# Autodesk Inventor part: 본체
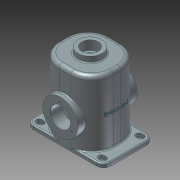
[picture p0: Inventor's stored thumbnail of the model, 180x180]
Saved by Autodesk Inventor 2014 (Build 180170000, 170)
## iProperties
Company: 한국ATC센터
Created: 2014-10
Part Number: 본체
Document SubType Name: Modeling
Designer: 한국ATC센터
Density: 2.71 g/cm^3
Material: 알루미늄 6061
Mass: 2952.11 g
Surface Area: 2149.43 cm^2
Volume: 1089.34 cm^3
Appearance: 청회색(연함)
Author: KYOUNG IL JANG
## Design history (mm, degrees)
sketch "스케치1"
  geometry: L1 (-70, 65)-(70, 65); L2 (70, 65)-(70, -65); L3 (70, -65)-(-70, -65); L4 (-70, -65)-(-70, 65); 3 further points
  constraints: 8 end point, 2 midpoint, 2 parallel, 1 horizontal, 1 horizontal alignment, 1 perpendicular, 1 vertical alignment
  dimensions: "d0" = 140 distance of L2.end L3.end; "d68" = 130 distance of L3.end L1.start
extrude "돌출1" new body sketch "스케치1" distance "d1" = 180; taper "d2" = 0 deg
fillet "모깎기1" dims "d3" = 55
feature "쉘1" dims "d4" = 10
sketch "스케치2"
  geometry: L1 (-70, 10)-(-70, -10) reference; L2 (-15, -65)-(-82, -65); L3 (-82, 65)-(-15, 65); L4 (-83, 57)-(-78, 57); L5 (-78, 41)-(-83, 41); L6 (-100, 47)-(-100, -47); A1 r 55 centre (-15, 10) between (-15, 65) and (-70, 10) reference; A2 r 55 centre (-15, -10) between (-70, -10) and (-15, -65) reference; A3 r 8 centre (-78, 49) between (-78, 41) and (-78, 57); A4 r 8 centre (-83, 49) between (-83, 57) and (-83, 41); A5 r 18 centre (-82, 47) between (-82, 65) and (-100, 47); A6 r 18 centre (-82, -47) between (-100, -47) and (-82, -65); 1 further point
  constraints: 10 end point, 9 tangent, 8 point on circle, 4 centre point, 2 parallel, 2 perpendicular, 1 equal radius
  dimensions: "d6" = 49 vertical distance of point (0, 0) A3.centre; "d8" = 16 distance between parallel lines of L4 L5; "d64" = 18 radius of A5; "d65" = 8 distance from line of A3.centre L1; "d66" = 30 distance between parallel lines of L6 L1; "d67" = 5 distance of A4.centre A3.centre
extrude "돌출2" join sketch "스케치2" distance "d9" = 10; taper "d10" = 0 deg
extrude "돌출3" cut sketch "스케치2" stored distance "d11" = 10; taper "d12" = 0 deg
sketch "스케치3"
  geometry: L1 (-65, 10)-(-65, 180) reference; L2 (-55, 0)-(-55, 170) reference; L3 (-77, 75)-(-45, 75); L4 (10, 0)-(-10, 0) reference; L5 (-77, 75)-(-77, 120.5); L6 (-77, 120.5)-(-55, 120.5); L7 (-55, 120.5)-(-45, 110.5); L8 (-45, 110.5)-(-45, 75); 3 further points
  constraints: 10 end point, 4 perpendicular, 1 point on line
  dimensions: "d13" = 75 distance between parallel lines of L3 L4; "d14" = 12 distance from line of L1 L3.start; "d15" = 10 distance from line of L3.end L2; "d16" = 91 diameter of L6 L3; "d17" = 135 deg angle of L7 L2
revolve "회전1" sketch "스케치3" stored, may be unused: angle "d18" = 90 deg
sketch "스케치4"
  geometry: C1 r 45.5 at (0, 0) reference; 2 further points
  constraints: 1 vertical alignment
  dimensions: "d19" = 35 distance of C1.centre point (0, 35)
hole "구멍1" sketch "스케치4" at (0, 35) diameter "d20" = 3.459; stored, may be unused: countersink angle "d24" = 90 deg, drill point angle "d26" = 118 deg; dims "d21" = 13, "d22" = 4, "d23" = 2, "d25" = 16
fillet "모깎기2" dims "d30" = 3
hole "구멍2" diameter "d33" = 52; stored, may be unused: countersink angle "d37" = 90 deg, drill point angle "d39" = 118 deg; dims "d31" = 10, "d32" = 10, "d34" = 13, "d35" = 4, "d36" = 2, "d38" = 16
sketch "스케치5"
  geometry: C1 r 31 at (0, 0); 1 further point
  constraints: 1 centre point, 1 coincident
  dimensions: "d40" = 62 diameter of C1
extrude "돌출4" join sketch "스케치5" distance "d41" = 15; taper "d42" = 0 deg
hole "구멍3" diameter "d45" = 43; stored, may be unused: countersink angle "d49" = 90 deg, drill point angle "d51" = 118 deg; dims "d43" = 10, "d44" = 10, "d46" = 13, "d47" = 4, "d48" = 2, "d50" = 16
fillet "모깎기3" dims "d52" = 3
fillet "모깎기4" dims "d53" = 3
chamfer "모따기1" distance "d55" = 1; stored, may be unused: second distance "d56" = 2, angle "d57" = 45 deg
sketch "스케치6"
  geometry: 2 further points
  constraints: 1 vertical alignment, 1 other
  dimensions: "d71" = 90 distance of point (0, 0) point (0, 90)
feature "엠보싱2" sketch "스케치6" dims "d0" = 140, "d68" = 130, "d72" = 1, "d73" = 0
fillet "모깎기6" dims "d74" = 10
sketch "스케치7"
  geometry: C1 r 15 at (0, 0); C2 r 21.5 at (0, 0) reference; C3 r 25 at (0, 0); 1 further point
  constraints: 2 centre point, 2 coincident
  dimensions: "d61" = 30 diameter of C1; "d75" = 50 diameter of C3
extrude "돌출5" join sketch "스케치7" distance "d62" = 10; taper "d63" = 0 deg
feature "면 이동1" dims "d76" = 1
node "솔리드1"
mirror "대칭1"
mirror "대칭2"
pattern_circular "원형 패턴1" dims angle "d28" = 360 deg
mirror "대칭3"
